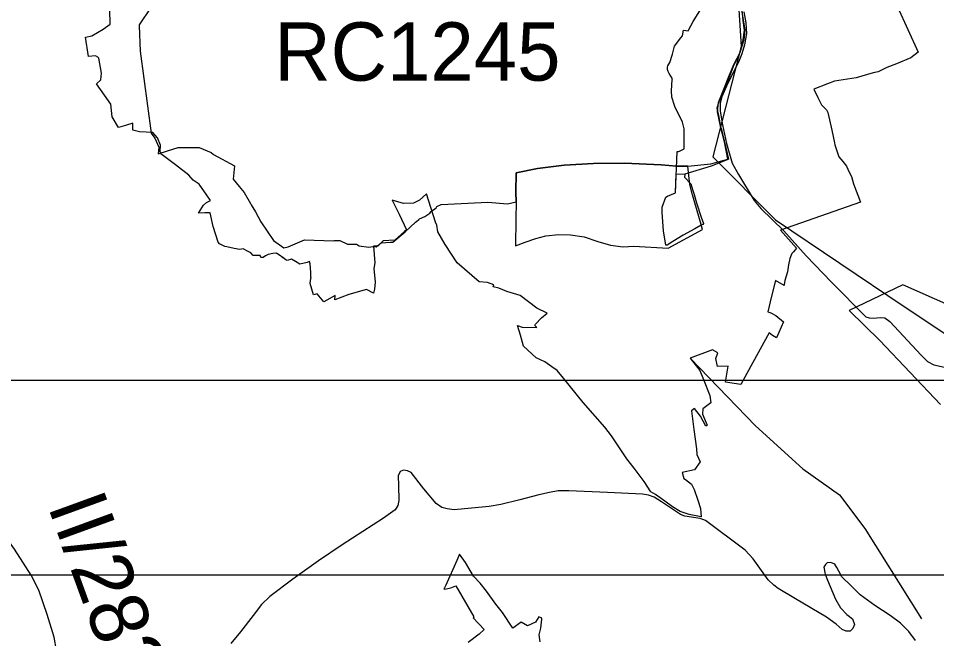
# Model space of a CAD drawing. Extents: x -789162 to -606354, y -1062736 to -945481.
# Drawn here: x -677802 to -675440, y -996142 to -994547 of the extents above; entities that cross this region are included whole.
import ezdxf

# ---------------------------------------------------------------- set-up
doc = ezdxf.new("R2010")
doc.units = 0
for name, color, linetype in [('_Rámeček', 7, 'Continuous'), ('_SIRSI VZTAHY_CYKLOTRASY MISTNI S', 7, 'Continuous'), ('_SIRSI VZTAHY_OP vodnich zdroju II stupne', 7, 'Continuous'), ('_SIRSI VZTAHY_SILNICE I a II TRIDY_STAV POPIS', 7, 'Continuous'), ('_SIRSI VZTAHY_SILNICE II TRIDY_STAV', 7, 'Continuous'), ('_SIRSI VZTAHY_SILNICE III TRIDY_STAV', 7, 'Continuous'), ('_SIRSI VZTAHY_USES_NRBK_S', 7, 'Continuous'), ('_SIRSI VZTAHY_USES_popis S', 7, 'Continuous'), ('_SIRSI VZTAHY_USES_RBC_S', 7, 'Continuous')]:
    doc.layers.add(name, color=color, linetype=linetype)

msp = doc.modelspace()

# ---------------------------------------------------------------- linework, layer by layer
at = {"layer": '_Rámeček'}
msp.add_line((-694376.9, -995477.3), (-674375.7, -995477.3), dxfattribs=at)
msp.add_lwpolyline([(-673887.2, -995977.3), (-673887.2, -966277.3), (-694887.2, -966277.3), (-694887.2, -995977.3)], close=True, dxfattribs=at)
at = {"layer": '_SIRSI VZTAHY_CYKLOTRASY MISTNI S'}
msp.add_lwpolyline([(-675110.9, -992821), (-675170.4, -992945.3), (-675538.4, -993211.1), (-675764.1, -993235.1), (-675762.5, -993314.6), (-675749.2, -993511.2), (-675656.4, -994101.7), (-675930, -994019.6), (-675998.4, -994098.3), (-675841, -994214.6), (-675964.2, -994279.6), (-675942.5, -994619), (-676015.5, -994902.4), (-675854.1, -995065), (-675523, -995287.3), (-675256.3, -995465.2), (-675085.3, -995663.7), (-675095.5, -995369.4), (-674873.3, -995605.5), (-674900.6, -996016.1)], dxfattribs=at)
at = {"layer": '_SIRSI VZTAHY_OP vodnich zdroju II stupne'}
for points in [[(-677460.8, -994519), (-677490.6, -994563.4), (-677490.9, -994566), (-677488.8, -994630.8), (-677460, -994842.2), (-677450.8, -994854.4), (-677440.8, -994877.6), (-677441.8, -994894.9), (-677418.3, -994887.6), (-677390.9, -994878.4), (-677337.1, -994878.3), (-677305.7, -994891.9), (-677299.8, -994896.4), (-677245.8, -994925.4), (-677249.2, -994959.8), (-677233.6, -994978.8), (-677220.6, -994994.4), (-677204.4, -995022.8), (-677202.6, -995026.3), (-677191.4, -995044.2), (-677178.4, -995069.5), (-677145.3, -995117.9), (-677119, -995136.5), (-677108.1, -995133.8), (-677066.1, -995115.8), (-676991.6, -995118.8), (-676988.3, -995118.1), (-676975.3, -995117.7), (-676954.9, -995127), (-676932.4, -995127.6), (-676924.8, -995131.5), (-676900.7, -995135.2), (-676890.4, -995133.4), (-676881.3, -995134.3), (-676868.4, -995123.6), (-676844.2, -995122.2), (-676838.4, -995121.8), (-676807.1, -995095.7), (-676780.2, -995071), (-676777.8, -995068.8), (-676771.6, -995063.7), (-676770, -995061.9), (-676756.6, -995055.7), (-676743.4, -995047.2), (-676739.8, -995043.6), (-676727.1, -995034.2), (-676725.8, -995030.7), (-676714.4, -995025.4), (-676594.3, -995019.2), (-676543.6, -995023.6), (-676521.6, -995018.1), (-676521.8, -994993.5), (-676521.4, -994944), (-676466.2, -994932.6), (-676397.6, -994923.8), (-676322.8, -994920), (-676242.3, -994918.8), (-676148, -994923.2), (-676108.6, -994927), (-676080, -994926.5), (-676021, -994921), (-675976.7, -994908.6), (-675985.2, -994864.3), (-675995.3, -994827.8), (-676003.9, -994786.6), (-676000.8, -994762.6), (-675989.1, -994733), (-675972.8, -994691.9), (-675960.4, -994663.1), (-675945.6, -994634.4), (-675937.1, -994601.8), (-675934, -994576.9), (-675937.1, -994552.1), (-675940.2, -994525.7)], [(-675941.6, -994524.4), (-675933.4, -994576.9), (-675935.6, -994601.8), (-675946.1, -994634.7), (-675960, -994663.3), (-675963.6, -994670.3), (-675981.5, -994718.9), (-675991.1, -994738.1), (-676000.6, -994763.4), (-676004.8, -994777.5), (-676001, -994796.6), (-675995, -994829.1), (-675994.4, -994828.9), (-675974.8, -994908.3), (-675976.7, -994909.2), (-676016.9, -994925.6), (-676020.1, -994926.8), (-676087.1, -994946.8), (-676088.5, -994955), (-676071.7, -994972.4), (-676066.9, -994989.2), (-676063.8, -994999.6), (-676057.1, -995020.6), (-676045.1, -995058.1), (-676039.1, -995074.3), (-676041.6, -995076.4), (-676045.4, -995078.2), (-676061.8, -995087.8), (-676091.9, -995104.2), (-676118.1, -995120.4), (-676132.9, -995129.4), (-676136.8, -995130.2), (-676142.6, -995093.2), (-676146.2, -995046.1), (-676145.5, -995032.1), (-676136.1, -995006.1), (-676132.2, -995004.2), (-676111.7, -994995.4), (-676106.8, -994889.1), (-676103.9, -994888.7), (-676101.6, -994888.4), (-676089.5, -994881.9), (-676089.5, -994830.6), (-676093.1, -994813.5), (-676113, -994773.6), (-676120.6, -994749.4), (-676122.2, -994732.5), (-676119.7, -994704.2), (-676119.2, -994702.2), (-676127.9, -994688.5), (-676130.8, -994682.8), (-676131.7, -994678), (-676131.8, -994671.8), (-676131, -994668.4), (-676126.4, -994660.2), (-676119.4, -994638.8), (-676113.8, -994618.1), (-676098.1, -994596.8), (-676093.1, -994591.2), (-676090.9, -994577.3), (-676079, -994578.7), (-676077.9, -994577.3), (-676066.5, -994554.9), (-676035.1, -994505.1)], [(-675408.3, -995284.3), (-675526.5, -995231.4), (-675665.1, -995297.4), (-675586.2, -995374.6), (-675429.7, -995539.8)], [(-676460, -996149.7), (-676462.4, -996132), (-676458.3, -996114.7), (-676455.6, -996091.6), (-676455.4, -996088.6), (-676463, -996085.5), (-676471.3, -996098.9), (-676492.5, -996108.9), (-676508.2, -996099.2), (-676529.7, -996114.6), (-676556.8, -996074.5), (-676573.7, -996052.9), (-676597.9, -996019.5), (-676614, -995998.9), (-676631, -995981.3), (-676651.8, -995946), (-676667.4, -995924.6), (-676674.1, -995940.7), (-676702.1, -996004.3), (-676705.9, -996011.2), (-676707.5, -996013.1), (-676704.9, -996014.8), (-676689.6, -996011.1), (-676676.3, -996005.7), (-676629.8, -996085.8), (-676631.9, -996087.9), (-676603.6, -996118.2), (-676616.6, -996129.9), (-676644.8, -996151.4)]]:
    msp.add_lwpolyline(points, dxfattribs=at)
for points in [[(-676219.1, -995132.5), (-676130.8, -995137.3), (-676042.2, -995089.9), (-676045.8, -995076.5), (-676067.9, -995000.7), (-676074.6, -994973.4), (-676080, -994926.5), (-676108.6, -994927), (-676148, -994923.2), (-676242.3, -994918.8), (-676322.8, -994920), (-676397.6, -994923.8), (-676466.2, -994932.6), (-676521.4, -994944), (-676521.8, -994993.5), (-676521.6, -995018.1), (-676521.8, -995063.1), (-676522.7, -995131.8), (-676498.2, -995121.9), (-676470.6, -995112.4), (-676444.8, -995106.1), (-676411.5, -995102.4), (-676381.3, -995103), (-676346.7, -995108), (-676310.9, -995120), (-676278.8, -995130), (-676246.1, -995134.4)], [(-676132.2, -995004.2), (-676111.7, -994995.4), (-676109.4, -994946.5), (-676087.1, -994946.8), (-676088.5, -994955), (-676071.7, -994972.4), (-676066.9, -994989.2), (-676063.8, -994999.6), (-676057.1, -995020.6), (-676045.1, -995058.1), (-676039.1, -995074.3), (-676041.6, -995076.4), (-676045.4, -995078.2), (-676061.8, -995087.8), (-676091.9, -995104.2), (-676118.1, -995120.4), (-676132.9, -995129.4), (-676136.8, -995130.2), (-676142.6, -995093.2), (-676146.2, -995046.1), (-676145.5, -995032.1), (-676136.1, -995006.1)]]:
    msp.add_lwpolyline(points, close=True, dxfattribs=at)
at = {"layer": '_SIRSI VZTAHY_SILNICE II TRIDY_STAV'}
msp.add_lwpolyline([(-677687.1, -996271.9), (-677691.9, -996242.6), (-677697.5, -996206.5), (-677710, -996137.8), (-677727.7, -996079.2), (-677749.3, -996016.6), (-677769.2, -995978.5), (-677811.5, -995911.6), (-677848.5, -995860.4), (-677905.4, -995773.2), (-677976.3, -995663.5), (-678050.5, -995540.8), (-678139.9, -995391.7), (-678174.2, -995336.8), (-678219.8, -995288.5), (-678246.5, -995260.2)], dxfattribs=at)
at = {"layer": '_SIRSI VZTAHY_SILNICE III TRIDY_STAV'}
for points in [[(-675935.4, -994530.1), (-675930.3, -994558.4), (-675929.1, -994585.3), (-675934.2, -994615), (-675940.5, -994637.7), (-675947.7, -994655.3), (-675980.5, -994721.2), (-675992.1, -994748.3), (-675996.8, -994764.3), (-675996.8, -994785.5), (-675991, -994820.6), (-675980.2, -994868.1), (-675965.8, -994918.8), (-675949.1, -994948.2), (-675909.4, -995014.6), (-675892.4, -995035.5), (-675832.9, -995093.2), (-675775.1, -995156.8), (-675710.6, -995225), (-675621.7, -995314.1), (-675613.5, -995316.9), (-675603.4, -995317.1), (-675584.4, -995315.4), (-675572.8, -995316.5), (-675560.3, -995326.3), (-675479.8, -995412.5), (-675463.6, -995428.9), (-675447.1, -995437.5), (-675412.2, -995444.8)], [(-675494.4, -996146.8), (-675511.1, -996123.1), (-675532.7, -996101.7), (-675559.2, -996081.9), (-675599, -996056.3), (-675636.3, -996029.1), (-675659.9, -996005.8), (-675683.6, -995982.4), (-675691.6, -995968), (-675696.2, -995958.7), (-675702.1, -995950.4), (-675711.9, -995945.6), (-675721.2, -995946.8), (-675726, -995951.2), (-675730.3, -995957.7), (-675726.8, -995976.2), (-675720.3, -995991.5), (-675699.9, -996040), (-675687.4, -996062.1), (-675670.7, -996079.2), (-675656.5, -996090.5), (-675651.5, -996105.6), (-675655.3, -996115.8), (-675662.5, -996122.6), (-675672.9, -996122.4), (-675683.2, -996117.9), (-675698.4, -996104.7), (-675723.3, -996086.6), (-675802.9, -996039.6), (-675847.7, -996012.9), (-675858.8, -996004.3), (-675872.8, -995990.4), (-675911.8, -995936.1), (-675932.2, -995914.4), (-676034.1, -995837.9), (-676047.7, -995832.9), (-676087.2, -995826.8), (-676098.5, -995822.4), (-676147.4, -995789.7), (-676166, -995777.5), (-676180.8, -995772.5), (-676196.8, -995769.7), (-676286.5, -995765.5), (-676385.9, -995761.1), (-676413.5, -995761.4), (-676435.8, -995765.8), (-676462.9, -995772.2), (-676511.6, -995784.6), (-676561.1, -995797), (-676591, -995801.7), (-676636.4, -995806.5), (-676680.8, -995810), (-676699.2, -995808.1), (-676712.9, -995804), (-676727.2, -995794.4), (-676758.5, -995756.4), (-676791.6, -995714.7), (-676800.5, -995709.8), (-676811.4, -995708.7), (-676819.9, -995712.2), (-676825, -995723.3), (-676824.1, -995747.6), (-676822.9, -995786.2), (-676825.9, -995798.9), (-676832.9, -995810.3), (-676862.8, -995831.6), (-676969.1, -995900.2), (-677029.4, -995941.1), (-677096, -995989), (-677155.3, -996033), (-677176.6, -996054), (-677198.2, -996082.1), (-677230.7, -996124), (-677255.5, -996154.5)]]:
    msp.add_lwpolyline(points, dxfattribs=at)
at = {"layer": '_SIRSI VZTAHY_USES_NRBK_S'}
msp.add_lwpolyline([(-676074.2, -995420.6), (-675905.5, -995594.1), (-675784.2, -995704.9), (-675690.1, -995771.7), (-675624.8, -995858.3), (-675479.2, -996090.6)], dxfattribs=at)
at = {"layer": '_SIRSI VZTAHY_USES_RBC_S'}
msp.add_lwpolyline([(-675540.2, -994517.1), (-675514, -994575.1), (-675487.7, -994633.2), (-675505.9, -994648.2), (-675543.4, -994663.5), (-675568.2, -994673), (-675590.6, -994684), (-675602.7, -994687), (-675646.4, -994699.1), (-675702.5, -994708.1), (-675720.7, -994715.1), (-675755.6, -994728.6), (-675745.2, -994750.2), (-675735.6, -994769.3), (-675723.4, -994781.6), (-675719.5, -994788.3), (-675709.5, -994834.2), (-675702.3, -994866.7), (-675701.3, -994872), (-675700.8, -994874.2), (-675695.8, -994889.5), (-675691.3, -994902.6), (-675681.5, -994914.6), (-675671.8, -994926.6), (-675664.5, -994941.8), (-675658.6, -994953.4), (-675653.9, -994972), (-675635.6, -995019), (-675841.5, -995090.9), (-675800, -995137.2), (-675808.1, -995147), (-675804.2, -995143.1), (-675812, -995150.8), (-675817.6, -995164.3), (-675821.2, -995180.4), (-675823.2, -995198.4), (-675830.5, -995220.8), (-675832.4, -995231.6), (-675831.7, -995233.9), (-675854.5, -995220.5), (-675864.2, -995260.9), (-675873.8, -995301.3), (-675866.7, -995304.1), (-675853.3, -995310.7), (-675833.5, -995326.8), (-675851.6, -995367.8), (-675861.7, -995361.7), (-675870.2, -995355.5), (-675912.2, -995431.1), (-675943.6, -995488), (-675983.1, -995482.4), (-675975.8, -995441.3), (-676003.4, -995441.4), (-676008.1, -995421.2), (-676003, -995406.5), (-676016.7, -995398.7), (-676074.2, -995420.6), (-676048.9, -995451.7), (-676039.4, -995475.6), (-676023, -995516.4), (-676020.7, -995535.6), (-676041.2, -995550.5), (-676041.7, -995564.5), (-676030.3, -995592.6), (-676033.7, -995595.6), (-676047, -995569.3), (-676062.3, -995550.2), (-676070, -995555.4), (-676064.2, -995603.8), (-676057.3, -995653.2), (-676056.5, -995668.2), (-676047.9, -995687.1), (-676063, -995707.7), (-676094.7, -995714.1), (-676090.4, -995729.5), (-676085.7, -995732), (-676070.4, -995744.5), (-676063.4, -995758.2), (-676053.9, -995785.2), (-676047, -995807), (-676045.1, -995828.6), (-676076, -995822.2), (-676099.2, -995815), (-676119.2, -995802.8), (-676139.3, -995788.1), (-676163.1, -995770.7), (-676175.3, -995764.4), (-676192.2, -995737.5), (-676199.8, -995727.5), (-676218.1, -995703.4), (-676236.4, -995679.4), (-676262, -995641), (-676276.1, -995619.8), (-676293.2, -995597.5), (-676348.7, -995534.3), (-676399.5, -995472.2), (-676415.5, -995451.9), (-676429.9, -995443), (-676447.8, -995430.2), (-676469.6, -995419.3), (-676502.5, -995389.6), (-676509.9, -995361.4), (-676518, -995336.6), (-676506.2, -995340.7), (-676468.6, -995341.1), (-676473.6, -995336.2), (-676471.8, -995333.2), (-676455.8, -995316.9), (-676441.9, -995305), (-676468.3, -995292.1), (-676511.2, -995259), (-676545.4, -995248.7), (-676565.6, -995240.4), (-676580.1, -995236.9), (-676578.9, -995231.4), (-676595, -995226.1), (-676616.3, -995224.2), (-676673.4, -995175), (-676704, -995127.7), (-676723.1, -995095.8), (-676725, -995078.6), (-676729.1, -995070.3), (-676752.2, -994998.1), (-676769.9, -995014.3), (-676785, -995022.2), (-676811.3, -995022.4), (-676840.4, -995014.3), (-676822, -995050.1), (-676803.1, -995090.3), (-676808.3, -995094.6), (-676833.5, -995116.9), (-676863.6, -995118.4), (-676877.5, -995132), (-676888.3, -995132.1), (-676885, -995175.1), (-676887.4, -995190.1), (-676883.8, -995224.6), (-676885.5, -995243.3), (-676888.7, -995253.4), (-676906.7, -995243.7), (-676951.7, -995256.3), (-676988, -995270.1), (-676986.8, -995259.4), (-677015.9, -995275.6), (-677033, -995254.6), (-677042.3, -995257.3), (-677051.2, -995228.2), (-677050, -995220.6), (-677048.8, -995213), (-677049.1, -995212.7), (-677049.6, -995200.3), (-677050.5, -995188.9), (-677051.4, -995177.4), (-677053.2, -995172.2), (-677059, -995174.2), (-677077.6, -995178.3), (-677077.6, -995178.6), (-677088.5, -995172.2), (-677099.5, -995166.2), (-677110.2, -995169.4), (-677114, -995167.1), (-677123.8, -995160.1), (-677121.2, -995161.8), (-677126.4, -995158.4), (-677137.4, -995150.7), (-677146.8, -995151.1), (-677159.3, -995153.6), (-677165.8, -995157.4), (-677172.3, -995161.3), (-677177.8, -995161.7), (-677179.9, -995156.5), (-677197.8, -995156.4), (-677204.2, -995149.1), (-677210.3, -995146.2), (-677223.9, -995139.6), (-677232.3, -995141), (-677246.3, -995138.4), (-677265.4, -995134.2), (-677270.8, -995133.2), (-677284.1, -995126.5), (-677287.4, -995122.1), (-677300.6, -995081.8), (-677308.5, -995047), (-677322.5, -995047), (-677338, -995047.1), (-677325.4, -995027.1), (-677317.9, -995020.1), (-677307.7, -995014.7), (-677316.6, -995001.2), (-677336.6, -994973.1), (-677352.5, -994962.8), (-677363.3, -994949.7), (-677397.9, -994923.4), (-677435.1, -994894.9), (-677436.9, -994889), (-677436.1, -994872.9), (-677444, -994854.1), (-677455.5, -994840.2), (-677489.8, -994838.1), (-677507.5, -994833.7), (-677506.9, -994816.3), (-677526, -994822.1), (-677543.8, -994827.1), (-677560.6, -994799.9), (-677564.3, -994767.2), (-677580.3, -994744.1), (-677600.4, -994715.1), (-677589.2, -994704.9), (-677588.1, -994687.1), (-677595.1, -994648.7), (-677597.4, -994646.3), (-677603.7, -994642.7), (-677621.4, -994644.7), (-677629.2, -994595.3), (-677612.8, -994591.9), (-677583.2, -994574.5), (-677565.2, -994561.6), (-677566.2, -994524.8)], dxfattribs=at)

# ---------------------------------------------------------------- texts
at = {"layer": '_SIRSI VZTAHY_SILNICE I a II TRIDY_STAV POPIS'}
msp.add_text('II/282', height=150, rotation=290.0248, dxfattribs=at).set_placement((-677727.2, -995800))
at = {"layer": '_SIRSI VZTAHY_USES_popis S'}
msp.add_text('RC1245', height=150, dxfattribs=at).set_placement((-677143.3, -994706.8))

doc.saveas('drawing.dxf')
